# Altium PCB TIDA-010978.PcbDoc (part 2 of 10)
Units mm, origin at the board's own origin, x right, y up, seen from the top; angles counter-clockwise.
Board outline 243.95 x 94.85 mm, 4 copper layers (Top Layer, Mid Layer 1, Mid Layer 2, Bottom Layer), stack 1.623 mm thick; 865 components, 374 nets, 2308 pads, 2132 vias.
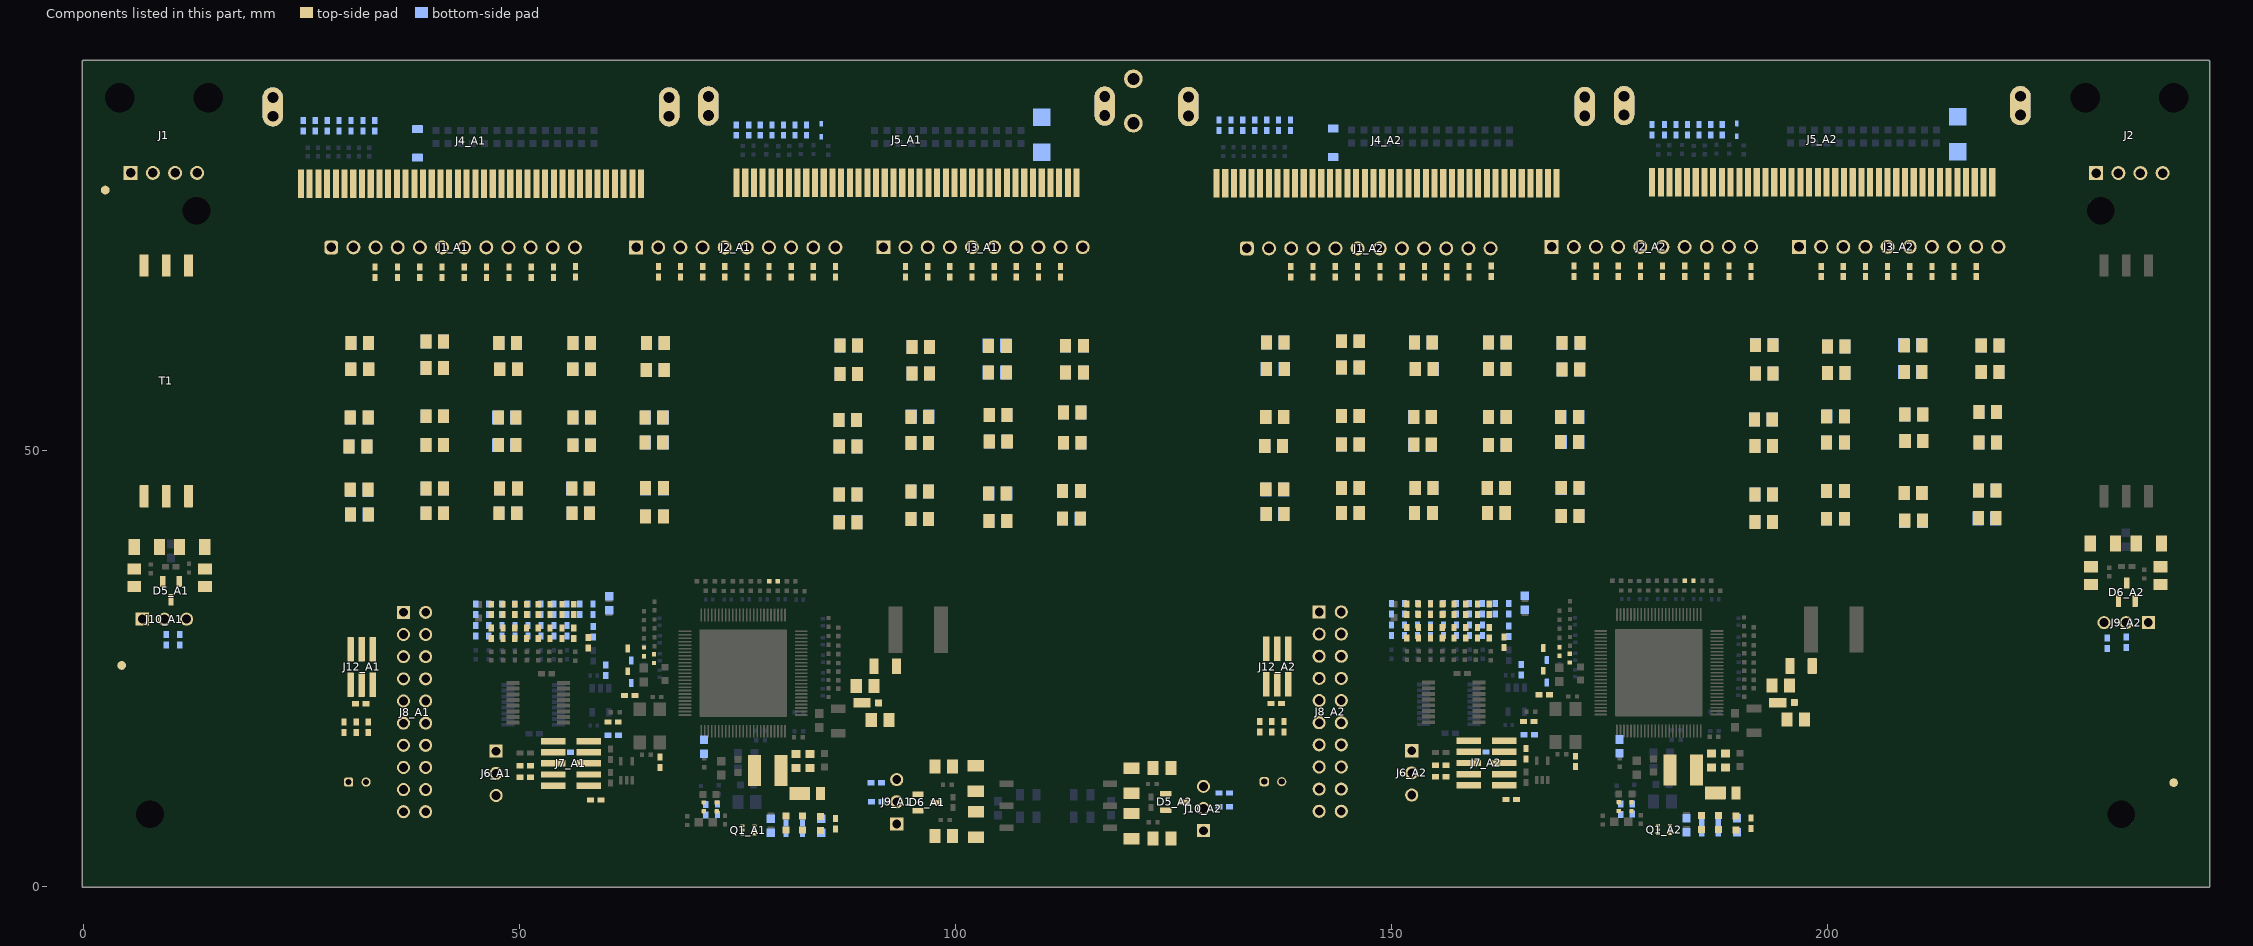
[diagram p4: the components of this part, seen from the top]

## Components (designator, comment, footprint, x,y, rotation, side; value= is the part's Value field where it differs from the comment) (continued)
C161_A2 "GCM155R71H104KE02D" 0402 165.428,15.207 r90 top value=0.1uF (schematic designator C161)
C162_A1 "885012205062" WCAP-CSGP_0402_L1W0.5H0.5 64.275,26.89 r90 top (schematic designator C162)
C162_A2 "885012205062" WCAP-CSGP_0402_L1W0.5H0.5 169.275,26.94 r90 top (schematic designator C162)
C163_A1 "885012205062" WCAP-CSGP_0402_L1W0.5H0.5 79.134,34.985 r0 top (schematic designator C163)
C163_A2 "885012205062" WCAP-CSGP_0402_L1W0.5H0.5 184.134,35.035 r0 top (schematic designator C163)
C164_A1 "885012205062" WCAP-CSGP_0402_L1W0.5H0.5 65.437,26.122 r90 top (schematic designator C164)
C164_A2 "885012205062" WCAP-CSGP_0402_L1W0.5H0.5 170.437,26.172 r90 top (schematic designator C164)
D1_A1 "SMAJ120A" SMA 109.917,86.187 r90 bottom value=120V (schematic designator D1)
D1_A2 "SMAJ120A" SMA 214.917,86.237 r90 bottom value=120V (schematic designator D1)
D2_A1 "MSP3V3-M3/89A" FP-MSP3V3-M3/89A_DO-219AD-MFG 89.932,21.045 r0 top (schematic designator D2)
D2_A2 "MSP3V3-M3/89A" FP-MSP3V3-M3/89A_DO-219AD-MFG 194.944,21.08 r0 top (schematic designator D2)
D3_A1 "DFLS1200Q-7" FP-DFLS1200Q-7_PowerDI123-MFG 82.994,10.671 r180 top (schematic designator D3)
D3_A2 "DFLS1200Q-7" FP-DFLS1200Q-7_PowerDI123-MFG 187.994,10.721 r180 top (schematic designator D3)
D4_A1 "TSD03DYFR" DYF0002A-MFG 62.822,24.614 r270 bottom (schematic designator D4)
D4_A2 "TSD03DYFR" DYF0002A-MFG 167.822,24.664 r270 bottom (schematic designator D4)
D5_A1 "ESD652DBZRQ1" DBZ0003A-MFG 10.044,33.917 r270 top (schematic designator D5)
D5_A2 "ESD652DBZRQ1" DBZ0003A-MFG 125.167,9.682 r0 top (schematic designator D5)
D6_A1 "ESD652DBZRQ1" DBZ0003A-MFG 96.754,9.621 r0 top (schematic designator D6)
D6_A2 "ESD652DBZRQ1" DBZ0003A-MFG 234.331,33.738 r90 top (schematic designator D6)
D7_A1 "SMD16PL-TP" FP-SMD16PL-TP_SOD123FL-MFG 38.313,85.209 r90 bottom (schematic designator D7)
D7_A2 "SMD16PL-TP" FP-SMD16PL-TP_SOD123FL-MFG 143.313,85.259 r90 bottom (schematic designator D7)
D8_A1 "TSD03DYFR" DYF0002A-MFG 62.422,25.974 r270 top (schematic designator D8)
D8_A2 "TSD03DYFR" DYF0002A-MFG 167.422,26.024 r270 top (schematic designator D8)
DVDD_LED1_A1 "150060GS75000" WL-SMCW_GREEN 82.479,7.262 r90 top value=Green (schematic designator DVDD_LED1)
DVDD_LED1_A2 "150060GS75000" WL-SMCW_GREEN 187.479,7.313 r90 top value=Green (schematic designator DVDD_LED1)
FID1 "Fiducial" Fiducial10-20 2.5,79.85 r0 top
FID2 "Fiducial" Fiducial10-20 4.373,25.336 r0 top
FID3 "Fiducial" Fiducial10-20 239.7,11.9 r0 top
H1 "MTG_NoPads" NPTH125mil 7.621,8.259 r0 top
H2 "MTG_NoPads" NPTH125mil 231.333,77.485 r0 top
H3 "MTG_NoPads" NPTH125mil 12.972,77.485 r0 top
H4 "MTG_NoPads" NPTH125mil 233.7,8.259 r0 top
J1 "70551-0038" Molex_70551-0038 9.23,81.81 r90 top
J1_A1 "61301211121" 61301211121 42.389,73.282 r0 top (schematic designator J1)
J1_A2 "61301211121" 61301211121 147.389,73.167 r0 top (schematic designator J1)
J2 "70551-0038" Molex_70551-0038 234.625,81.8 r90 top
J2_A1 "61301011121" Wurth_61301011121 74.803,73.282 r0 top (schematic designator J2)
J2_A2 "61301011121" Wurth_61301011121 179.803,73.332 r0 top (schematic designator J2)
J3_A1 "61301011121" Wurth_61301011121 103.165,73.295 r0 top (schematic designator J3)
J3_A2 "61301011121" Wurth_61301011121 208.165,73.345 r0 top (schematic designator J3)
J4_A1 "141114-214010" FP-141114-214010_HDR40-MFG 44.442,88.287 r180 top (schematic designator J4)
J4_A2 "141114-214010" FP-141114-214010_HDR40-MFG 149.442,88.337 r180 top (schematic designator J4)
J5_A1 "141115-214010" FP-141114-214010_HDR40-MFG 94.392,88.387 r180 top (schematic designator J5)
J5_A2 "141115-214010" FP-141114-214010_HDR40-MFG 199.392,88.437 r180 top (schematic designator J5)
J6_A1 "PEC03SAAN" CONN_PEC03SAAN 47.323,12.961 r270 top (schematic designator J6)
J6_A2 "PEC03SAAN" CONN_PEC03SAAN 152.323,13.011 r270 top (schematic designator J6)
J7_A1 "FTSH-105-01-L-DV-K" Samtec_FTSH-105-01-x-DV-K 55.895,14.101 r180 top (schematic designator J7)
J7_A2 "FTSH-105-01-L-DV-K" Samtec_FTSH-105-01-x-DV-K 160.895,14.151 r180 top (schematic designator J7)
J8_A1 "PRPC010DAAN-RC" Sullins_xxxC010DAAN 37.973,19.991 r0 top (schematic designator J8)
J8_A2 "PRPC010DAAN-RC" Sullins_xxxC010DAAN 142.973,20.041 r0 top (schematic designator J8)
J9_A1 "PEC03SAAN" CONN_PEC03SAAN 93.264,9.702 r90 top (schematic designator J9)
J9_A2 "PEC03SAAN" CONN_PEC03SAAN 234.25,30.248 r180 top (schematic designator J9)
J10_A1 "PEC03SAAN" CONN_PEC03SAAN 9.287,30.642 r0 top (schematic designator J10)
J10_A2 "PEC03SAAN" CONN_PEC03SAAN 128.442,8.926 r90 top (schematic designator J10)
J11_A1 "B2B-PH-K-S(LF)(SN)" JST_B2B-PH-K-S 31.413,11.405 r0 top (schematic designator J11)
J11_A2 "B2B-PH-K-S(LF)(SN)" JST_B2B-PH-K-S 136.413,11.455 r0 top (schematic designator J11)
J12_A1 "FTSH-103-01-L-DV-K" FP-FTSH-103-01-F-DV-TR_HDR6-MFG 31.901,25.161 r180 top (schematic designator J12)
J12_A2 "FTSH-103-01-L-DV-K" FP-FTSH-103-01-F-DV-TR_HDR6-MFG 136.901,25.211 r180 top (schematic designator J12)
j13 "63824-1" FP-63824-1_CONN_7MM92_3MM11-MFG 120.4,90.062 r270 top (schematic designator J13)
L2_A1 "74404042101" WE-LQS_4018 78.468,13.29 r180 top (schematic designator L2)
L2_A2 "74404042101" WE-LQS_4018 183.468,13.34 r180 top (schematic designator L2)
LBL1 "THT-14-423-10" Label_650x200 219.021,6.766 r0 top
LDOIN_LED1_A1 "150060GS75000" WL-SMCW_GREEN 80.571,7.262 r90 top value=Green (schematic designator LDOIN_LED1)
LDOIN_LED1_A2 "150060GS75000" WL-SMCW_GREEN 185.571,7.313 r90 top value=Green (schematic designator LDOIN_LED1)
Logo1 "Texas Instruments" TI_Stacked_Overlay_Small 218.143,28.378 r0 top
Logo2 "CE Mark" CE_Mark_5mm 217.099,15.808 r0 top
Logo3 "FCC disclaimer" FCC_disclaimer 216.878,2.683 r0 top
Logo4 "WEEE logo" WEEE_Minimum 224.561,16.126 r0 top
LOGO5 "DANGER HIGH VOLTAGE" IEC_HighVoltage_Small 209.565,16.126 r0 top
NFAULT_LED1_A1 "150060RS75000" WL-SMCW_RED 84.517,7.212 r90 top value=Red (schematic designator NFAULT_LED1)
NFAULT_LED1_A2 "150060RS75000" WL-SMCW_RED 189.517,7.263 r90 top value=Red (schematic designator NFAULT_LED1)
Q1_A1 "SSM6L56FE,LM" FP-SSM6L56FE,LM_SOT563-MFG 76.262,6.465 r270 top (schematic designator Q1)
Q1_A2 "SSM6L56FE,LM" FP-SSM6L56FE,LM_SOT563-MFG 181.262,6.515 r270 top (schematic designator Q1)
R1_A1 "CRCW080528R0FKEA" 0805_HV 89.642,22.984 r0 top value=28.0 (schematic designator R1)
R1_A2 "CRCW080528R0FKEA" 0805_HV 194.642,23.034 r0 top value=28.0 (schematic designator R1)
R2_A1 "HPCR0805J68R0KT" 0805_HV 48.674,42.787 r0 top value=68 (schematic designator R2)
R2_A2 "HPCR0805J68R0KT" 0805_HV 153.674,42.837 r0 top value=68 (schematic designator R2)
R3_A1 "HPCR0805J68R0KT" 0805_HV 65.486,45.662 r0 top value=68 (schematic designator R3)
R3_A2 "HPCR0805J68R0KT" 0805_HV 170.486,45.712 r0 top value=68 (schematic designator R3)
R4_A1 "HPCR0805J68R0KT" 0805_HV 95.914,42.111 r0 bottom value=68 (schematic designator R4)
R4_A2 "HPCR0805J68R0KT" 0805_HV 200.914,42.161 r0 bottom value=68 (schematic designator R4)
R5_A1 "HPCR0805J68R0KT" 0805_HV 113.313,45.358 r0 top value=68 (schematic designator R5)
R5_A2 "HPCR0805J68R0KT" 0805_HV 218.313,45.408 r0 top value=68 (schematic designator R5)
R6_A1 "CRCW120662R0JNEAHP" FP-CRCW120662R0JNEAHP_1206-MFG 91.952,25.245 r0 top value=62 (schematic designator R6)
R6_A2 "CRCW120662R0JNEAHP" FP-CRCW120662R0JNEAHP_1206-MFG 196.979,25.277 r0 top value=62 (schematic designator R6)
R7_A1 "CRCW080551R0JNEA" 0805_HV 91.358,19.092 r180 top value=51 (schematic designator R7)
R7_A2 "CRCW080551R0JNEA" 0805_HV 196.358,19.142 r180 top value=51 (schematic designator R7)
R8_A1 "HPCR0805J68R0KT" 0805_HV 48.744,45.646 r0 top value=68 (schematic designator R8)
R8_A2 "HPCR0805J68R0KT" 0805_HV 153.744,45.696 r0 top value=68 (schematic designator R8)
R9_A1 "HPCR0805J68R0KT" 0805_HV 65.486,42.446 r0 bottom value=68 (schematic designator R9)
R9_A2 "HPCR0805J68R0KT" 0805_HV 170.486,42.496 r0 bottom value=68 (schematic designator R9)
R10_A1 "HPCR0805J68R0KT" 0805_HV 95.914,45.279 r0 top value=68 (schematic designator R10)
R10_A2 "HPCR0805J68R0KT" 0805_HV 200.914,45.329 r0 top value=68 (schematic designator R10)
R11_A1 "HPCR0805J68R0KT" 0805_HV 113.313,42.205 r0 top value=68 (schematic designator R11)
R11_A2 "HPCR0805J68R0KT" 0805_HV 218.313,42.255 r0 top value=68 (schematic designator R11)
R12_A1 "HPCR0805J68R0KT" 0805_HV 48.674,42.787 r0 bottom value=68 (schematic designator R12)
R12_A2 "HPCR0805J68R0KT" 0805_HV 153.674,42.837 r0 bottom value=68 (schematic designator R12)
R13_A1 "HPCR0805J68R0KT" 0805_HV 65.486,45.646 r0 bottom value=68 (schematic designator R13)
R13_A2 "HPCR0805J68R0KT" 0805_HV 170.486,45.696 r0 bottom value=68 (schematic designator R13)
R14_A1 "HPCR0805J68R0KT" 0805_HV 95.914,45.279 r0 bottom value=68 (schematic designator R14)
R14_A2 "HPCR0805J68R0KT" 0805_HV 200.914,45.329 r0 bottom value=68 (schematic designator R14)
R15_A1 "HPCR0805J68R0KT" 0805_HV 113.273,42.157 r0 bottom value=68 (schematic designator R15)
R15_A2 "HPCR0805J68R0KT" 0805_HV 218.273,42.207 r0 bottom value=68 (schematic designator R15)
R16_A1 "HPCR0805J68R0KT" 0805_HV 48.744,45.646 r0 bottom value=68 (schematic designator R16)
R16_A2 "HPCR0805J68R0KT" 0805_HV 153.744,45.696 r0 bottom value=68 (schematic designator R16)
R17_A1 "HPCR0805J68R0KT" 0805_HV 65.486,42.437 r0 top value=68 (schematic designator R17)
R17_A2 "HPCR0805J68R0KT" 0805_HV 170.486,42.487 r0 top value=68 (schematic designator R17)
R18_A1 "HPCR0805J68R0KT" 0805_HV 95.914,42.111 r0 top value=68 (schematic designator R18)
R18_A2 "HPCR0805J68R0KT" 0805_HV 200.914,42.161 r0 top value=68 (schematic designator R18)
R19_A1 "HPCR0805J68R0KT" 0805_HV 113.313,45.325 r0 bottom value=68 (schematic designator R19)
R19_A2 "HPCR0805J68R0KT" 0805_HV 218.313,45.375 r0 bottom value=68 (schematic designator R19)
R20_A1 "DNP" 0603 82.507,13.585 r180 top value=10 (schematic designator R20)
R20_A2 "DNP" 0603 187.507,13.635 r180 top value=10 (schematic designator R20)
R21_A1 "HPCR0805J68R0KT" 0805_HV 40.291,59.461 r0 top value=68 (schematic designator R21)
R21_A2 "HPCR0805J68R0KT" 0805_HV 145.291,59.511 r0 top value=68 (schematic designator R21)
R22_A1 "HPCR0805J68R0KT" 0805_HV 57.146,62.305 r0 top value=68 (schematic designator R22)
R22_A2 "HPCR0805J68R0KT" 0805_HV 162.146,62.355 r0 top value=68 (schematic designator R22)
R23_A1 "HPCR0805J68R0KT" 0805_HV 87.758,58.747 r0 top value=68 (schematic designator R23)
R23_A2 "HPCR0805J68R0KT" 0805_HV 192.758,58.797 r0 top value=68 (schematic designator R23)
R24_A1 "HPCR0805J68R0KT" 0805_HV 104.828,58.946 r0 top value=68 (schematic designator R24)
R24_A2 "HPCR0805J68R0KT" 0805_HV 209.828,58.996 r0 top value=68 (schematic designator R24)
R25_A1 "HPCR0805J68R0KT" 0805_HV 40.291,62.462 r0 bottom value=68 (schematic designator R25)
R25_A2 "HPCR0805J68R0KT" 0805_HV 145.291,62.512 r0 bottom value=68 (schematic designator R25)
R26_A1 "HPCR0805J68R0KT" 0805_HV 57.129,59.305 r0 top value=68 (schematic designator R26)
R26_A2 "HPCR0805J68R0KT" 0805_HV 162.129,59.355 r0 top value=68 (schematic designator R26)
R27_A1 "HPCR0805J68R0KT" 0805_HV 87.758,62.003 r0 top value=68 (schematic designator R27)
R27_A2 "HPCR0805J68R0KT" 0805_HV 192.758,62.053 r0 top value=68 (schematic designator R27)
R28_A1 "HPCR0805J68R0KT" 0805_HV 104.748,58.946 r0 bottom value=68 (schematic designator R28)
R28_A2 "HPCR0805J68R0KT" 0805_HV 209.748,58.996 r0 bottom value=68 (schematic designator R28)
R29_A1 "HPCR0805J68R0KT" 0805_HV 40.291,59.461 r0 bottom value=68 (schematic designator R29)
R29_A2 "HPCR0805J68R0KT" 0805_HV 145.291,59.511 r0 bottom value=68 (schematic designator R29)
R30_A1 "HPCR0805J68R0KT" 0805_HV 57.129,59.305 r0 bottom value=68 (schematic designator R30)
R30_A2 "HPCR0805J68R0KT" 0805_HV 162.129,59.355 r0 bottom value=68 (schematic designator R30)
R31_A1 "HPCR0805J68R0KT" 0805_HV 87.758,58.747 r0 bottom value=68 (schematic designator R31)
R31_A2 "HPCR0805J68R0KT" 0805_HV 192.758,58.797 r0 bottom value=68 (schematic designator R31)
R32_A1 "HPCR0805J68R0KT" 0805_HV 104.748,62.012 r0 bottom value=68 (schematic designator R32)
R32_A2 "HPCR0805J68R0KT" 0805_HV 209.748,62.062 r0 bottom value=68 (schematic designator R32)
R33_A1 "HPCR0805J68R0KT" 0805_HV 40.291,62.462 r0 top value=68 (schematic designator R33)
R33_A2 "HPCR0805J68R0KT" 0805_HV 145.291,62.512 r0 top value=68 (schematic designator R33)
R34_A1 "HPCR0805J68R0KT" 0805_HV 57.146,62.305 r0 bottom value=68 (schematic designator R34)
R34_A2 "HPCR0805J68R0KT" 0805_HV 162.146,62.355 r0 bottom value=68 (schematic designator R34)
R35_A1 "HPCR0805J68R0KT" 0805_HV 87.758,62.012 r0 bottom value=68 (schematic designator R35)
R35_A2 "HPCR0805J68R0KT" 0805_HV 192.758,62.062 r0 bottom value=68 (schematic designator R35)
R36_A1 "HPCR0805J68R0KT" 0805_HV 104.828,61.969 r0 top value=68 (schematic designator R36)
R36_A2 "HPCR0805J68R0KT" 0805_HV 209.828,62.019 r0 top value=68 (schematic designator R36)
R37_A1 "RC0603FR-07120RL" 0603 71.159,16.004 r270 bottom value=120 (schematic designator R37)
R37_A2 "RC0603FR-07120RL" 0603 176.159,16.054 r270 bottom value=120 (schematic designator R37)
R38_A1 "HPCR0805J68R0KT" 0805_HV 40.291,50.603 r0 top value=68 (schematic designator R38)
R38_A2 "HPCR0805J68R0KT" 0805_HV 145.291,50.653 r0 top value=68 (schematic designator R38)
R39_A1 "HPCR0805J68R0KT" 0805_HV 57.146,53.755 r0 top value=68 (schematic designator R39)
R39_A2 "HPCR0805J68R0KT" 0805_HV 162.146,53.805 r0 top value=68 (schematic designator R39)
R40_A1 "HPCR0805J68R0KT" 0805_HV 87.688,50.464 r0 top value=68 (schematic designator R40)
R40_A2 "HPCR0805J68R0KT" 0805_HV 192.688,50.514 r0 top value=68 (schematic designator R40)
R41_A1 "HPCR0805J68R0KT" 0805_HV 104.915,54.059 r0 top value=68 (schematic designator R41)
R41_A2 "HPCR0805J68R0KT" 0805_HV 209.915,54.109 r0 top value=68 (schematic designator R41)
R42_A1 "HPCR0805J68R0KT" 0805_HV 40.291,53.912 r0 top value=68 (schematic designator R42)
R42_A2 "HPCR0805J68R0KT" 0805_HV 145.291,53.962 r0 top value=68 (schematic designator R42)
R43_A1 "HPCR0805J68R0KT" 0805_HV 57.146,50.587 r0 top value=68 (schematic designator R43)
R43_A2 "HPCR0805J68R0KT" 0805_HV 162.146,50.637 r0 top value=68 (schematic designator R43)
R44_A1 "HPCR0805J68R0KT" 0805_HV 87.649,53.464 r0 top value=68 (schematic designator R44)
R44_A2 "HPCR0805J68R0KT" 0805_HV 192.649,53.514 r0 top value=68 (schematic designator R44)
R45_A1 "HPCR0805J68R0KT" 0805_HV 104.857,51.025 r0 bottom value=68 (schematic designator R45)
R45_A2 "HPCR0805J68R0KT" 0805_HV 209.857,51.075 r0 bottom value=68 (schematic designator R45)
R46_A1 "HPCR0805J68R0KT" 0805_HV 40.291,53.912 r0 bottom value=68 (schematic designator R46)
R46_A2 "HPCR0805J68R0KT" 0805_HV 145.291,53.962 r0 bottom value=68 (schematic designator R46)
R47_A1 "HPCR0805J68R0KT" 0805_HV 57.146,53.755 r0 bottom value=68 (schematic designator R47)
R47_A2 "HPCR0805J68R0KT" 0805_HV 162.146,53.805 r0 bottom value=68 (schematic designator R47)
R48_A1 "HPCR0805J68R0KT" 0805_HV 87.688,50.464 r0 bottom value=68 (schematic designator R48)
R48_A2 "HPCR0805J68R0KT" 0805_HV 192.688,50.514 r0 bottom value=68 (schematic designator R48)
R49_A1 "HPCR0805J68R0KT" 0805_HV 104.877,54.059 r0 bottom value=68 (schematic designator R49)
R49_A2 "HPCR0805J68R0KT" 0805_HV 209.877,54.109 r0 bottom value=68 (schematic designator R49)
R50_A1 "ERJ-3GEY0R00V" 0603 82.507,15.19 r0 top value=0 (schematic designator R50)
R50_A2 "ERJ-3GEY0R00V" 0603 187.507,15.24 r0 top value=0 (schematic designator R50)
R51_A1 "HPCR0805J68R0KT" 0805_HV 40.291,50.603 r0 bottom value=68 (schematic designator R51)
R51_A2 "HPCR0805J68R0KT" 0805_HV 145.291,50.653 r0 bottom value=68 (schematic designator R51)
R52_A1 "HPCR0805J68R0KT" 0805_HV 57.146,50.587 r0 bottom value=68 (schematic designator R52)
R52_A2 "HPCR0805J68R0KT" 0805_HV 162.146,50.637 r0 bottom value=68 (schematic designator R52)
R53_A1 "HPCR0805J68R0KT" 0805_HV 87.649,53.464 r0 bottom value=68 (schematic designator R53)
R53_A2 "HPCR0805J68R0KT" 0805_HV 192.649,53.514 r0 bottom value=68 (schematic designator R53)
R54_A1 "HPCR0805J68R0KT" 0805_HV 104.941,51.025 r0 top value=68 (schematic designator R54)
R54_A2 "HPCR0805J68R0KT" 0805_HV 209.941,51.075 r0 top value=68 (schematic designator R54)
R55_A1 "ERJ-2RKF10R0X" FP-ERJ-2RKF10R0X_0402-MFG 71.154,9.122 r270 top (schematic designator R55)
R55_A2 "ERJ-2RKF10R0X" FP-ERJ-2RKF10R0X_0402-MFG 176.056,9.14 r270 top (schematic designator R55)
R56_A1 "CRCW040210K2FKED" 0402 60.767,17.341 r180 bottom value=10.2k (schematic designator R56)
R56_A2 "CRCW040210K2FKED" 0402 165.817,17.391 r180 bottom value=10.2k (schematic designator R56)
R57_A1 "ERJ-2RKF10R0X" FP-ERJ-2RKF10R0X_0402-MFG 72.629,9.121 r270 top (schematic designator R57)
R57_A2 "ERJ-2RKF10R0X" FP-ERJ-2RKF10R0X_0402-MFG 177.531,9.137 r270 top (schematic designator R57)
R58_A1 "HPCR0805J68R0KT" 0805_HV 40.291,42.787 r0 top value=68 (schematic designator R58)
R58_A2 "HPCR0805J68R0KT" 0805_HV 145.291,42.837 r0 top value=68 (schematic designator R58)
R59_A1 "HPCR0805J68R0KT" 0805_HV 57.03,45.637 r0 top value=68 (schematic designator R59)
R59_A2 "HPCR0805J68R0KT" 0805_HV 162.03,45.687 r0 top value=68 (schematic designator R59)
R60_A1 "HPCR0805J68R0KT" 0805_HV 87.688,44.914 r0 bottom value=68 (schematic designator R60)
R60_A2 "HPCR0805J68R0KT" 0805_HV 192.688,44.964 r0 bottom value=68 (schematic designator R60)
R61_A1 "HPCR0805J68R0KT" 0805_HV 104.866,45.078 r0 bottom value=68 (schematic designator R61)
R61_A2 "HPCR0805J68R0KT" 0805_HV 209.866,45.128 r0 bottom value=68 (schematic designator R61)
R62_A1 "HPCR0805J68R0KT" 0805_HV 40.291,42.787 r0 bottom value=68 (schematic designator R62)
R62_A2 "HPCR0805J68R0KT" 0805_HV 145.291,42.837 r0 bottom value=68 (schematic designator R62)
R63_A1 "HPCR0805J68R0KT" 0805_HV 57.03,42.787 r0 bottom value=68 (schematic designator R63)
R63_A2 "HPCR0805J68R0KT" 0805_HV 162.03,42.837 r0 bottom value=68 (schematic designator R63)
R64_A1 "HPCR0805J68R0KT" 0805_HV 87.688,41.746 r0 top value=68 (schematic designator R64)
R64_A2 "HPCR0805J68R0KT" 0805_HV 192.688,41.796 r0 top value=68 (schematic designator R64)
R65_A1 "HPCR0805J68R0KT" 0805_HV 104.782,45.078 r0 top value=68 (schematic designator R65)
R65_A2 "HPCR0805J68R0KT" 0805_HV 209.782,45.128 r0 top value=68 (schematic designator R65)
R66_A1 "HPCR0805J68R0KT" 0805_HV 40.291,45.646 r0 top value=68 (schematic designator R66)
R66_A2 "HPCR0805J68R0KT" 0805_HV 145.291,45.696 r0 top value=68 (schematic designator R66)
R67_A1 "HPCR0805J68R0KT" 0805_HV 57.03,42.787 r0 top value=68 (schematic designator R67)
R67_A2 "HPCR0805J68R0KT" 0805_HV 162.03,42.837 r0 top value=68 (schematic designator R67)
R68_A1 "HPCR0805J68R0KT" 0805_HV 87.688,44.914 r0 top value=68 (schematic designator R68)
R68_A2 "HPCR0805J68R0KT" 0805_HV 192.688,44.964 r0 top value=68 (schematic designator R68)
R69_A1 "HPCR0805J68R0KT" 0805_HV 104.857,41.876 r0 bottom value=68 (schematic designator R69)
R69_A2 "HPCR0805J68R0KT" 0805_HV 209.857,41.926 r0 bottom value=68 (schematic designator R69)
R70_A1 "ERJ-2GE0R00X" 0402 59.887,24.806 r90 bottom value=0 (schematic designator R70)
R70_A2 "ERJ-2GE0R00X" 0402 164.887,24.856 r90 bottom value=0 (schematic designator R70)
R71_A1 "ERJ-2GE0R00X" 0402 66.111,14.231 r270 top value=0 (schematic designator R71)
R71_A2 "ERJ-2GE0R00X" 0402 171.104,14.321 r270 top value=0 (schematic designator R71)
R72_A1 "HPCR0805J68R0KT" 0805_HV 40.291,45.637 r0 bottom value=68 (schematic designator R72)
R72_A2 "HPCR0805J68R0KT" 0805_HV 145.291,45.687 r0 bottom value=68 (schematic designator R72)
R73_A1 "HPCR0805J68R0KT" 0805_HV 56.964,45.646 r0 bottom value=68 (schematic designator R73)
R73_A2 "HPCR0805J68R0KT" 0805_HV 161.964,45.696 r0 bottom value=68 (schematic designator R73)
R74_A1 "HPCR0805J68R0KT" 0805_HV 87.688,41.762 r0 bottom value=68 (schematic designator R74)
R74_A2 "HPCR0805J68R0KT" 0805_HV 192.688,41.812 r0 bottom value=68 (schematic designator R74)
R75_A1 "HPCR0805J68R0KT" 0805_HV 104.877,41.925 r0 top value=68 (schematic designator R75)
R75_A2 "HPCR0805J68R0KT" 0805_HV 209.877,41.975 r0 top value=68 (schematic designator R75)
R76_A1 "CRCW040210K2FKED" 0402 60.728,18.845 r0 top value=10.2k (schematic designator R76)
R76_A2 "CRCW040210K2FKED" 0402 165.728,18.895 r0 top value=10.2k (schematic designator R76)
R77_A1 "ERJ-2GE0R00X" 0402 62.667,21.882 r180 top value=0 (schematic designator R77)
R77_A2 "ERJ-2GE0R00X" 0402 167.515,21.964 r180 top value=0 (schematic designator R77)
R78_A1 "ERJ-2GE0R00X" 0402 71.375,8.812 r270 bottom value=0 (schematic designator R78)
R78_A2 "ERJ-2GE0R00X" 0402 176.287,8.861 r270 bottom value=0 (schematic designator R78)
R79_A1 "ERJ-2GE0R00X" 0402 86.233,7.167 r90 top value=0 (schematic designator R79)
R79_A2 "ERJ-2GE0R00X" 0402 191.233,7.217 r90 top value=0 (schematic designator R79)
R80_A1 "HPCR0805J68R0KT" 0805_HV 31.65,59.305 r0 bottom value=68 (schematic designator R80)
R80_A2 "HPCR0805J68R0KT" 0805_HV 136.65,59.355 r0 bottom value=68 (schematic designator R80)
R81_A1 "HPCR0805J68R0KT" 0805_HV 48.744,59.305 r0 top value=68 (schematic designator R81)
R81_A2 "HPCR0805J68R0KT" 0805_HV 153.744,59.355 r0 top value=68 (schematic designator R81)
R82_A1 "HPCR0805J68R0KT" 0805_HV 65.559,59.227 r0 top value=68 (schematic designator R82)
R82_A2 "HPCR0805J68R0KT" 0805_HV 170.559,59.277 r0 top value=68 (schematic designator R82)
R83_A1 "HPCR0805J68R0KT" 0805_HV 96.01,61.844 r0 top value=68 (schematic designator R83)
R83_A2 "HPCR0805J68R0KT" 0805_HV 201.01,61.894 r0 top value=68 (schematic designator R83)
R84_A1 "HPCR0805J68R0KT" 0805_HV 113.651,58.928 r0 top value=68 (schematic designator R84)
R84_A2 "HPCR0805J68R0KT" 0805_HV 218.651,58.978 r0 top value=68 (schematic designator R84)
R85_A1 "HPCR0805J68R0KT" 0805_HV 31.679,62.305 r0 bottom value=68 (schematic designator R85)
R85_A2 "HPCR0805J68R0KT" 0805_HV 136.679,62.355 r0 bottom value=68 (schematic designator R85)
R86_A1 "HPCR0805J68R0KT" 0805_HV 48.662,62.305 r0 top value=68 (schematic designator R86)
R86_A2 "HPCR0805J68R0KT" 0805_HV 153.662,62.355 r0 top value=68 (schematic designator R86)
R87_A1 "HPCR0805J68R0KT" 0805_HV 65.59,62.292 r0 top value=68 (schematic designator R87)
R87_A2 "HPCR0805J68R0KT" 0805_HV 170.59,62.342 r0 top value=68 (schematic designator R87)
R88_A1 "HPCR0805J68R0KT" 0805_HV 96.015,58.821 r0 top value=68 (schematic designator R88)
R88_A2 "HPCR0805J68R0KT" 0805_HV 201.015,58.871 r0 top value=68 (schematic designator R88)
R89_A1 "HPCR0805J68R0KT" 0805_HV 113.651,61.996 r0 top value=68 (schematic designator R89)
R89_A2 "HPCR0805J68R0KT" 0805_HV 218.651,62.046 r0 top value=68 (schematic designator R89)
R90_A1 "HPCR0805J68R0KT" 0805_HV 31.679,62.305 r0 top value=68 (schematic designator R90)
R90_A2 "HPCR0805J68R0KT" 0805_HV 136.679,62.355 r0 top value=68 (schematic designator R90)
R91_A1 "HPCR0805J68R0KT" 0805_HV 48.78,59.305 r0 bottom value=68 (schematic designator R91)
R91_A2 "HPCR0805J68R0KT" 0805_HV 153.78,59.355 r0 bottom value=68 (schematic designator R91)
R92_A1 "HPCR0805J68R0KT" 0805_HV 65.59,59.227 r0 bottom value=68 (schematic designator R92)
R92_A2 "HPCR0805J68R0KT" 0805_HV 170.59,59.277 r0 bottom value=68 (schematic designator R92)
R93_A1 "HPCR0805J68R0KT" 0805_HV 96.015,58.821 r0 bottom value=68 (schematic designator R93)
R93_A2 "HPCR0805J68R0KT" 0805_HV 201.015,58.871 r0 bottom value=68 (schematic designator R93)
R94_A1 "HPCR0805J68R0KT" 0805_HV 113.651,61.996 r0 bottom value=68 (schematic designator R94)
R94_A2 "HPCR0805J68R0KT" 0805_HV 218.651,62.046 r0 bottom value=68 (schematic designator R94)
R95_A1 "HPCR0805J68R0KT" 0805_HV 31.704,59.305 r0 top value=68 (schematic designator R95)
R95_A2 "HPCR0805J68R0KT" 0805_HV 136.704,59.355 r0 top value=68 (schematic designator R95)
R96_A1 "HPCR0805J68R0KT" 0805_HV 48.638,62.305 r0 bottom value=68 (schematic designator R96)
R96_A2 "HPCR0805J68R0KT" 0805_HV 153.638,62.355 r0 bottom value=68 (schematic designator R96)
R97_A1 "HPCR0805J68R0KT" 0805_HV 65.59,62.283 r0 bottom value=68 (schematic designator R97)
R97_A2 "HPCR0805J68R0KT" 0805_HV 170.59,62.333 r0 bottom value=68 (schematic designator R97)
R98_A1 "HPCR0805J68R0KT" 0805_HV 96.015,61.844 r0 bottom value=68 (schematic designator R98)
R98_A2 "HPCR0805J68R0KT" 0805_HV 201.015,61.894 r0 bottom value=68 (schematic designator R98)
R99_A1 "HPCR0805J68R0KT" 0805_HV 113.651,58.928 r0 bottom value=68 (schematic designator R99)
R99_A2 "HPCR0805J68R0KT" 0805_HV 218.651,58.978 r0 bottom value=68 (schematic designator R99)
R100_A1 "HPCR0805J68R0KT" 0805_HV 31.602,53.755 r0 top value=68 (schematic designator R100)
R100_A2 "HPCR0805J68R0KT" 0805_HV 136.602,53.805 r0 top value=68 (schematic designator R100)
R101_A1 "HPCR0805J68R0KT" 0805_HV 48.524,50.587 r0 bottom value=68 (schematic designator R101)
R101_A2 "HPCR0805J68R0KT" 0805_HV 153.524,50.637 r0 bottom value=68 (schematic designator R101)
R102_A1 "HPCR0805J68R0KT" 0805_HV 65.472,53.79 r0 bottom value=68 (schematic designator R102)
R102_A2 "HPCR0805J68R0KT" 0805_HV 170.472,53.84 r0 bottom value=68 (schematic designator R102)
R103_A1 "HPCR0805J68R0KT" 0805_HV 95.914,53.829 r0 top value=68 (schematic designator R103)
R103_A2 "HPCR0805J68R0KT" 0805_HV 200.914,53.879 r0 top value=68 (schematic designator R103)
R104_A1 "HPCR0805J68R0KT" 0805_HV 113.388,54.34 r0 top value=68 (schematic designator R104)
R104_A2 "HPCR0805J68R0KT" 0805_HV 218.388,54.39 r0 top value=68 (schematic designator R104)
R105_A1 "ERJ-2GE0R00X" 0402 72.697,8.826 r90 bottom value=0 (schematic designator R105)
R105_A2 "ERJ-2GE0R00X" 0402 177.609,8.874 r90 bottom value=0 (schematic designator R105)
R107_A1 "HPCR0805J68R0KT" 0805_HV 31.48,50.446 r0 top value=68 (schematic designator R107)
R107_A2 "HPCR0805J68R0KT" 0805_HV 136.48,50.496 r0 top value=68 (schematic designator R107)
R108_A1 "HPCR0805J68R0KT" 0805_HV 48.59,53.755 r0 top value=68 (schematic designator R108)
R108_A2 "HPCR0805J68R0KT" 0805_HV 153.59,53.805 r0 top value=68 (schematic designator R108)
R109_A1 "HPCR0805J68R0KT" 0805_HV 65.416,53.79 r0 top value=68 (schematic designator R109)
R109_A2 "HPCR0805J68R0KT" 0805_HV 170.416,53.84 r0 top value=68 (schematic designator R109)
R110_A1 "HPCR0805J68R0KT" 0805_HV 95.946,53.862 r0 bottom value=68 (schematic designator R110)
R110_A2 "HPCR0805J68R0KT" 0805_HV 200.946,53.912 r0 bottom value=68 (schematic designator R110)
R111_A1 "HPCR0805J68R0KT" 0805_HV 113.388,50.874 r0 top value=68 (schematic designator R111)
R111_A2 "HPCR0805J68R0KT" 0805_HV 218.388,50.924 r0 top value=68 (schematic designator R111)
R112_A1 "HPCR0805J68R0KT" 0805_HV 31.65,53.755 r0 bottom value=68 (schematic designator R112)
R112_A2 "HPCR0805J68R0KT" 0805_HV 136.65,53.805 r0 bottom value=68 (schematic designator R112)
R113_A1 "HPCR0805J68R0KT" 0805_HV 48.59,50.603 r0 top value=68 (schematic designator R113)
R113_A2 "HPCR0805J68R0KT" 0805_HV 153.59,50.653 r0 top value=68 (schematic designator R113)
R114_A1 "HPCR0805J68R0KT" 0805_HV 65.416,50.915 r0 top value=68 (schematic designator R114)
R114_A2 "HPCR0805J68R0KT" 0805_HV 170.416,50.965 r0 top value=68 (schematic designator R114)
R115_A1 "HPCR0805J68R0KT" 0805_HV 95.914,50.828 r0 bottom value=68 (schematic designator R115)
R115_A2 "HPCR0805J68R0KT" 0805_HV 200.914,50.878 r0 bottom value=68 (schematic designator R115)
R116_A1 "HPCR0805J68R0KT" 0805_HV 113.388,50.874 r0 bottom value=68 (schematic designator R116)
R116_A2 "HPCR0805J68R0KT" 0805_HV 218.388,50.924 r0 bottom value=68 (schematic designator R116)
R117_A1 "HPCR0805J68R0KT" 0805_HV 31.48,50.446 r0 bottom value=68 (schematic designator R117)
R117_A2 "HPCR0805J68R0KT" 0805_HV 136.48,50.496 r0 bottom value=68 (schematic designator R117)
R118_A1 "HPCR0805J68R0KT" 0805_HV 48.524,53.755 r0 bottom value=68 (schematic designator R118)
R118_A2 "HPCR0805J68R0KT" 0805_HV 153.524,53.805 r0 bottom value=68 (schematic designator R118)
R119_A1 "HPCR0805J68R0KT" 0805_HV 65.486,50.915 r0 bottom value=68 (schematic designator R119)
R119_A2 "HPCR0805J68R0KT" 0805_HV 170.486,50.965 r0 bottom value=68 (schematic designator R119)
R120_A1 "HPCR0805J68R0KT" 0805_HV 95.914,50.828 r0 top value=68 (schematic designator R120)
R120_A2 "HPCR0805J68R0KT" 0805_HV 200.914,50.878 r0 top value=68 (schematic designator R120)
R121_A1 "HPCR0805J68R0KT" 0805_HV 113.388,54.34 r0 bottom value=68 (schematic designator R121)
R121_A2 "HPCR0805J68R0KT" 0805_HV 218.388,54.39 r0 bottom value=68 (schematic designator R121)
R122_A1 "HPCR0805J68R0KT" 0805_HV 31.602,45.489 r0 top value=68 (schematic designator R122)
R122_A2 "HPCR0805J68R0KT" 0805_HV 136.602,45.539 r0 top value=68 (schematic designator R122)
R123_A1 "HPCR0805J68R0KT" 0805_HV 31.629,42.63 r0 bottom value=68 (schematic designator R123)
R123_A2 "HPCR0805J68R0KT" 0805_HV 136.629,42.68 r0 bottom value=68 (schematic designator R123)
R124_A1 "HPCR0805J68R0KT" 0805_HV 31.629,45.48 r0 bottom value=68 (schematic designator R124)
R124_A2 "HPCR0805J68R0KT" 0805_HV 136.629,45.53 r0 bottom value=68 (schematic designator R124)
R125_A1 "HPCR0805J68R0KT" 0805_HV 31.654,42.63 r0 top value=68 (schematic designator R125)
R125_A2 "HPCR0805J68R0KT" 0805_HV 136.654,42.68 r0 top value=68 (schematic designator R125)
R126_A1 "RC0402FR-074K7L" 0402 82.468,6.66 r270 bottom value=4.70k (schematic designator R126)
R126_A2 "RC0402FR-074K7L" 0402 187.468,6.71 r270 bottom value=4.70k (schematic designator R126)
R127_A1 "ESR03EZPJ102" 0603 60.292,32.471 r270 bottom value=1.0k (schematic designator R127)
R127_A2 "ESR03EZPJ102" 0603 165.292,32.521 r270 bottom value=1.0k (schematic designator R127)
R128_A1 "ESR03EZPJ102" 0603 78.833,6.964 r90 bottom value=1.0k (schematic designator R128)
R128_A2 "ESR03EZPJ102" 0603 183.833,7.014 r90 bottom value=1.0k (schematic designator R128)
R129_A1 "RC0402FR-074K7L" 0402 80.572,6.66 r270 bottom value=4.70k (schematic designator R129)
R129_A2 "RC0402FR-074K7L" 0402 185.572,6.71 r270 bottom value=4.70k (schematic designator R129)
R130_A1 "ESR03EZPJ102" 0603 84.624,6.964 r270 bottom value=1.0k (schematic designator R130)
R130_A2 "ESR03EZPJ102" 0603 189.624,7.014 r270 bottom value=1.0k (schematic designator R130)
R131_A1 "CRCW040210K0FKED" 0402 53.926,31.771 r90 bottom value=10.0k (schematic designator R131)
R131_A2 "CRCW040210K0FKED" 0402 158.926,31.821 r90 bottom value=10.0k (schematic designator R131)
R132_A1 "CRCW040210K0FKED" 0402 52.438,31.771 r90 bottom value=10.0k (schematic designator R132)
R132_A2 "CRCW040210K0FKED" 0402 157.438,31.821 r90 bottom value=10.0k (schematic designator R132)
R133_A1 "CRCW040210K0FKED" 0402 50.95,31.771 r90 bottom value=10.0k (schematic designator R133)
R133_A2 "CRCW040210K0FKED" 0402 155.95,31.821 r90 bottom value=10.0k (schematic designator R133)
R134_A1 "CRCW040210K0FKED" 0402 55.414,31.771 r90 bottom value=10.0k (schematic designator R134)
R134_A2 "CRCW040210K0FKED" 0402 160.414,31.821 r90 bottom value=10.0k (schematic designator R134)
R135_A1 "CRCW040210K0FKED" 0402 49.462,31.771 r90 bottom value=10.0k (schematic designator R135)
R135_A2 "CRCW040210K0FKED" 0402 154.462,31.821 r90 bottom value=10.0k (schematic designator R135)
R136_A1 "CRCW040210K0FKED" 0402 44.997,31.771 r90 bottom value=10.0k (schematic designator R136)
R136_A2 "CRCW040210K0FKED" 0402 149.997,31.821 r90 bottom value=10.0k (schematic designator R136)
R137_A1 "CRCW040210K0FKED" 0402 47.974,31.771 r90 bottom value=10.0k (schematic designator R137)
R137_A2 "CRCW040210K0FKED" 0402 152.974,31.821 r90 bottom value=10.0k (schematic designator R137)
R138_A1 "CRCW040210K0FKED" 0402 46.486,31.771 r90 bottom value=10.0k (schematic designator R138)
R138_A2 "CRCW040210K0FKED" 0402 151.486,31.821 r90 bottom value=10.0k (schematic designator R138)
R140_A1 "CRCW04021K00JNED" 0402 46.491,29.301 r90 bottom value=1.0k (schematic designator R140)
R140_A2 "CRCW04021K00JNED" 0402 151.491,29.351 r90 bottom value=1.0k (schematic designator R140)
R141_A1 "CRCW04021K00JNED" 0402 76.298,86.737 r90 bottom value=1.0k (schematic designator R141)
R141_A2 "CRCW04021K00JNED" 0402 181.298,86.787 r90 bottom value=1.0k (schematic designator R141)
R143_A1 "CRCW04021K00JNED" 0402 47.984,29.301 r90 bottom value=1.0k (schematic designator R143)
R143_A2 "CRCW04021K00JNED" 0402 152.984,29.351 r90 bottom value=1.0k (schematic designator R143)
R144_A1 "AC0402FR-07100KL" 0402 77.624,86.737 r90 bottom value=100k (schematic designator R144)
R144_A2 "AC0402FR-07100KL" 0402 182.624,86.787 r90 bottom value=100k (schematic designator R144)
R146_A1 "CRCW04021K00JNED" 0402 44.997,29.301 r90 bottom value=1.0k (schematic designator R146)
R146_A2 "CRCW04021K00JNED" 0402 149.997,29.351 r90 bottom value=1.0k (schematic designator R146)
R147_A1 "CRCW04021K00JNED" 0402 74.867,86.737 r90 bottom value=1.0k (schematic designator R147)
R147_A2 "CRCW04021K00JNED" 0402 179.867,86.787 r90 bottom value=1.0k (schematic designator R147)
R149_A1 "CRCW04021K00JNED" 0402 49.477,29.301 r90 bottom value=1.0k (schematic designator R149)
R149_A2 "CRCW04021K00JNED" 0402 154.477,29.351 r90 bottom value=1.0k (schematic designator R149)
R150_A1 "AC0402FR-07100KL" 0402 78.951,86.737 r90 bottom value=100k (schematic designator R150)
R150_A2 "AC0402FR-07100KL" 0402 183.951,86.787 r90 bottom value=100k (schematic designator R150)
R152_A1 "CRCW04021K00JNED" 0402 55.451,29.301 r90 bottom value=1.0k (schematic designator R152)
R152_A2 "CRCW04021K00JNED" 0402 160.451,29.351 r90 bottom value=1.0k (schematic designator R152)
R153_A1 "RC0402FR-074K7L" 0402 56.902,31.771 r270 bottom value=4.70k (schematic designator R153)
R153_A2 "RC0402FR-074K7L" 0402 161.902,31.821 r270 bottom value=4.70k (schematic designator R153)
R155_A1 "AC0402FR-07100KL" 0402 50.665,12.523 r180 top value=100k (schematic designator R155)
R155_A2 "AC0402FR-07100KL" 0402 155.665,12.573 r180 top value=100k (schematic designator R155)
R156_A1 "CRCW04021K00JNED" 0402 50.971,29.301 r90 bottom value=1.0k (schematic designator R156)
R156_A2 "CRCW04021K00JNED" 0402 155.971,29.351 r90 bottom value=1.0k (schematic designator R156)
R157_A1 "AC0402FR-07100KL" 0402 80.277,86.737 r90 bottom value=100k (schematic designator R157)
R157_A2 "AC0402FR-07100KL" 0402 185.277,86.787 r90 bottom value=100k (schematic designator R157)
R159_A1 "CRCW04021K00JNED" 0402 52.464,29.301 r90 bottom value=1.0k (schematic designator R159)
R159_A2 "CRCW04021K00JNED" 0402 157.464,29.351 r90 bottom value=1.0k (schematic designator R159)
R160_A1 "CRCW04021K00JNED" 0402 81.603,86.737 r90 bottom value=1.0k (schematic designator R160)
R160_A2 "CRCW04021K00JNED" 0402 186.603,86.787 r90 bottom value=1.0k (schematic designator R160)
R162_A1 "AC0402FR-07100KL" 0402 50.65,13.845 r180 top value=100k (schematic designator R162)
R162_A2 "AC0402FR-07100KL" 0402 155.65,13.895 r180 top value=100k (schematic designator R162)
R163_A1 "CRCW04021K00JNED" 0402 53.958,29.301 r90 bottom value=1.0k (schematic designator R163)
R163_A2 "CRCW04021K00JNED" 0402 158.958,29.351 r90 bottom value=1.0k (schematic designator R163)
R164_A1 "AC0402FR-07100KL" 0402 82.93,86.737 r90 bottom value=100k (schematic designator R164)
R164_A2 "AC0402FR-07100KL" 0402 187.93,86.787 r90 bottom value=100k (schematic designator R164)
R165_A1 "AC0402FR-07100KL" 0402 58.746,9.902 r180 top value=100k (schematic designator R165)
R165_A2 "AC0402FR-07100KL" 0402 163.746,9.952 r180 top value=100k (schematic designator R165)
R166_A1 "AC0402FR-07100KL" 0402 57.61,16.627 r180 bottom value=100k (schematic designator R166)
R166_A2 "AC0402FR-07100KL" 0402 162.61,16.677 r180 bottom value=100k (schematic designator R166)
R167_A1 "AC0402FR-07100KL" 0402 56.43,15.371 r180 bottom value=100k (schematic designator R167)
R167_A2 "AC0402FR-07100KL" 0402 161.43,15.421 r180 bottom value=100k (schematic designator R167)
R168_A1 "CRCW040210K0FKED" 0402 54.867,31.753 r90 top value=10.0k (schematic designator R168)
R168_A2 "CRCW040210K0FKED" 0402 159.867,31.803 r90 top value=10.0k (schematic designator R168)
R169_A1 "CRCW040210K0FKED" 0402 53.515,31.753 r90 top value=10.0k (schematic designator R169)
R169_A2 "CRCW040210K0FKED" 0402 158.515,31.803 r90 top value=10.0k (schematic designator R169)
R170_A1 "CRCW040210K0FKED" 0402 52.164,31.753 r90 top value=10.0k (schematic designator R170)
R170_A2 "CRCW040210K0FKED" 0402 157.164,31.803 r90 top value=10.0k (schematic designator R170)
R171_A1 "CRCW040210K0FKED" 0402 56.218,31.753 r90 top value=10.0k (schematic designator R171)
R171_A2 "CRCW040210K0FKED" 0402 161.218,31.803 r90 top value=10.0k (schematic designator R171)
R172_A1 "CRCW040210K0FKED" 0402 50.813,31.753 r90 top value=10.0k (schematic designator R172)
R172_A2 "CRCW040210K0FKED" 0402 155.813,31.803 r90 top value=10.0k (schematic designator R172)
R173_A1 "CRCW040210K0FKED" 0402 46.759,31.753 r90 top value=10.0k (schematic designator R173)
R173_A2 "CRCW040210K0FKED" 0402 151.759,31.803 r90 top value=10.0k (schematic designator R173)
R174_A1 "CRCW040210K0FKED" 0402 49.462,31.753 r90 top value=10.0k (schematic designator R174)
R174_A2 "CRCW040210K0FKED" 0402 154.462,31.803 r90 top value=10.0k (schematic designator R174)
R175_A1 "CRCW040210K0FKED" 0402 48.11,31.753 r90 top value=10.0k (schematic designator R175)
R175_A2 "CRCW040210K0FKED" 0402 153.11,31.803 r90 top value=10.0k (schematic designator R175)
R176_A1 "CRCW04021K00JNED" 0402 48.11,29.051 r90 top value=1.0k (schematic designator R176)
R176_A2 "CRCW04021K00JNED" 0402 153.11,29.101 r90 top value=1.0k (schematic designator R176)
R177_A1 "CRCW04021K00JNED" 0402 26.584,87.212 r90 bottom value=1.0k (schematic designator R177)
R177_A2 "CRCW04021K00JNED" 0402 131.584,87.262 r90 bottom value=1.0k (schematic designator R177)
R178_A1 "CRCW04021K00JNED" 0402 49.462,29.051 r90 top value=1.0k (schematic designator R178)
R178_A2 "CRCW04021K00JNED" 0402 154.462,29.101 r90 top value=1.0k (schematic designator R178)
R179_A1 "AC0402FR-07100KL" 0402 27.951,87.212 r90 bottom value=100k (schematic designator R179)
R179_A2 "AC0402FR-07100KL" 0402 132.951,87.262 r90 bottom value=100k (schematic designator R179)
R180_A1 "CRCW04021K00JNED" 0402 46.759,29.051 r90 top value=1.0k (schematic designator R180)
R180_A2 "CRCW04021K00JNED" 0402 151.759,29.101 r90 top value=1.0k (schematic designator R180)
R181_A1 "CRCW04021K00JNED" 0402 25.217,87.212 r90 bottom value=1.0k (schematic designator R181)
R181_A2 "CRCW04021K00JNED" 0402 130.217,87.262 r90 bottom value=1.0k (schematic designator R181)
R182_A1 "CRCW04021K00JNED" 0402 50.813,29.051 r90 top value=1.0k (schematic designator R182)
R182_A2 "CRCW04021K00JNED" 0402 155.813,29.101 r90 top value=1.0k (schematic designator R182)
R183_A1 "AC0402FR-07100KL" 0402 29.317,87.212 r90 bottom value=100k (schematic designator R183)
R183_A2 "AC0402FR-07100KL" 0402 134.317,87.262 r90 bottom value=100k (schematic designator R183)
R184_A1 "CRCW04021K00JNED" 0402 56.218,29.051 r90 top value=1.0k (schematic designator R184)
R184_A2 "CRCW04021K00JNED" 0402 161.218,29.101 r90 top value=1.0k (schematic designator R184)
R185_A1 "RC0402FR-074K7L" 0402 57.902,27.934 r90 top value=4.70k (schematic designator R185)
R185_A2 "RC0402FR-074K7L" 0402 162.902,27.984 r90 top value=4.70k (schematic designator R185)
R186_A1 "CRCW04021K00JNED" 0402 52.164,29.051 r90 top value=1.0k (schematic designator R186)
R186_A2 "CRCW04021K00JNED" 0402 157.164,29.101 r90 top value=1.0k (schematic designator R186)
R187_A1 "AC0402FR-07100KL" 0402 30.684,87.212 r90 bottom value=100k (schematic designator R187)
R187_A2 "AC0402FR-07100KL" 0402 135.684,87.262 r90 bottom value=100k (schematic designator R187)
R188_A1 "CRCW04021K00JNED" 0402 53.515,29.051 r90 top value=1.0k (schematic designator R188)
R188_A2 "CRCW04021K00JNED" 0402 158.515,29.101 r90 top value=1.0k (schematic designator R188)
R189_A1 "CRCW04021K00JNED" 0402 32.051,87.212 r90 bottom value=1.0k (schematic designator R189)
R189_A2 "CRCW04021K00JNED" 0402 137.051,87.262 r90 bottom value=1.0k (schematic designator R189)
R190_A1 "CRCW04021K00JNED" 0402 54.867,29.051 r90 top value=1.0k (schematic designator R190)
R190_A2 "CRCW04021K00JNED" 0402 159.867,29.101 r90 top value=1.0k (schematic designator R190)
R191_A1 "AC0402FR-07100KL" 0402 33.417,87.212 r90 bottom value=100k (schematic designator R191)
R191_A2 "AC0402FR-07100KL" 0402 138.417,87.262 r90 bottom value=100k (schematic designator R191)
R192_A1 "CRCW04021K00FKED" 0402 73.548,70.467 r270 top value=1.00k (schematic designator R192)
R192_A2 "CRCW04021K00FKED" 0402 178.548,70.517 r270 top value=1.00k (schematic designator R192)
R193_A1 "CRCW040210K0FKED" 0402 58.446,31.771 r90 bottom value=10.0k (schematic designator R193)
R193_A2 "CRCW040210K0FKED" 0402 163.446,31.821 r90 bottom value=10.0k (schematic designator R193)
R194_A1 "CRCW04021K00FKED" 0402 71.011,70.467 r270 top value=1.00k (schematic designator R194)
R194_A2 "CRCW04021K00FKED" 0402 176.011,70.517 r270 top value=1.00k (schematic designator R194)
R195_A1 "CRCW04021K00FKED" 0402 112.055,70.462 r270 top value=1.00k (schematic designator R195)
R195_A2 "CRCW04021K00FKED" 0402 217.055,70.512 r270 top value=1.00k (schematic designator R195)
R196_A1 "CRCW04021K00JNED" 0402 58.452,29.184 r90 bottom value=1.0k (schematic designator R196)
R196_A2 "CRCW04021K00JNED" 0402 163.452,29.234 r90 bottom value=1.0k (schematic designator R196)
R197_A1 "CRCW04021K00FKED" 0402 68.474,70.467 r270 top value=1.00k (schematic designator R197)
R197_A2 "CRCW04021K00FKED" 0402 173.474,70.517 r270 top value=1.00k (schematic designator R197)
R198_A1 "CRCW04021K00FKED" 0402 109.515,70.462 r270 top value=1.00k (schematic designator R198)
R198_A2 "CRCW04021K00FKED" 0402 214.515,70.512 r270 top value=1.00k (schematic designator R198)
R199_A1 "CRCW04021K00FKED" 0402 65.936,70.467 r270 top value=1.00k (schematic designator R199)
R199_A2 "CRCW04021K00FKED" 0402 170.936,70.517 r270 top value=1.00k (schematic designator R199)
R200_A1 "CRCW04021K00FKED" 0402 106.975,70.462 r270 top value=1.00k (schematic designator R200)
R200_A2 "CRCW04021K00FKED" 0402 211.975,70.512 r270 top value=1.00k (schematic designator R200)
R201_A1 "CRCW04021K00FKED" 0402 56.438,70.467 r270 top value=1.00k (schematic designator R201)
R201_A2 "CRCW04021K00FKED" 0402 161.438,70.517 r270 top value=1.00k (schematic designator R201)
R202_A1 "CRCW04021K00FKED" 0402 104.435,70.462 r270 top value=1.00k (schematic designator R202)
R202_A2 "CRCW04021K00FKED" 0402 209.435,70.512 r270 top value=1.00k (schematic designator R202)
R203_A1 "CRCW04021K00FKED" 0402 53.906,70.432 r270 top value=1.00k (schematic designator R203)
R203_A2 "CRCW04021K00FKED" 0402 158.906,70.482 r270 top value=1.00k (schematic designator R203)
R204_A1 "CRCW04021K00FKED" 0402 101.895,70.462 r270 top value=1.00k (schematic designator R204)
R204_A2 "CRCW04021K00FKED" 0402 206.895,70.512 r270 top value=1.00k (schematic designator R204)
R205_A1 "CRCW04021K00FKED" 0402 51.348,70.432 r270 top value=1.00k (schematic designator R205)
R205_A2 "CRCW04021K00FKED" 0402 156.348,70.482 r270 top value=1.00k (schematic designator R205)
R206_A1 "CRCW04021K00FKED" 0402 99.355,70.462 r270 top value=1.00k (schematic designator R206)
R206_A2 "CRCW04021K00FKED" 0402 204.355,70.512 r270 top value=1.00k (schematic designator R206)
R207_A1 "CRCW04021K00FKED" 0402 48.791,70.432 r270 top value=1.00k (schematic designator R207)
R207_A2 "CRCW04021K00FKED" 0402 153.791,70.482 r270 top value=1.00k (schematic designator R207)
R208_A1 "CRCW04021K00FKED" 0402 96.815,70.462 r270 top value=1.00k (schematic designator R208)
R208_A2 "CRCW04021K00FKED" 0402 201.815,70.512 r270 top value=1.00k (schematic designator R208)
R209_A1 "ERJ-2GE0R00X" 0402 11.056,28.259 r270 bottom value=0 (schematic designator R209)
R209_A2 "ERJ-2GE0R00X" 0402 130.825,10.694 r0 bottom value=0 (schematic designator R209)
R210_A1 "ERJ-6GEYJ100V" 0805_HV 13.923,35.399 r270 top value=10 (schematic designator R210)
R210_A2 "ERJ-6GEYJ100V" 0805_HV 123.685,13.562 r0 top value=10 (schematic designator R210)
R211_A1 "ERJ-2GE0R00X" 0402 90.906,11.874 r0 bottom value=0 (schematic designator R211)
R211_A2 "ERJ-2GE0R00X" 0402 232.079,27.89 r90 bottom value=0 (schematic designator R211)
R212_A1 "ERJ-6GEYJ100V" 0805_HV 98.654,13.727 r0 top value=10 (schematic designator R212)
R212_A2 "ERJ-6GEYJ100V" 0805_HV 230.226,35.638 r90 top value=10 (schematic designator R212)
R213_A1 "CRCW04021K00FKED" 0402 46.233,70.432 r270 top value=1.00k (schematic designator R213)
R213_A2 "CRCW04021K00FKED" 0402 151.233,70.482 r270 top value=1.00k (schematic designator R213)
R214_A1 "CRCW04021K00FKED" 0402 94.275,70.462 r270 top value=1.00k (schematic designator R214)
R214_A2 "CRCW04021K00FKED" 0402 199.275,70.512 r270 top value=1.00k (schematic designator R214)
R215_A1 "ERJ-8ENF80R6V" 1206 12.473,38.907 r0 top value=80.6 (schematic designator R215)
R215_A2 "ERJ-8ENF80R6V" 1206 120.177,12.112 r90 top value=80.6 (schematic designator R215)
R216_A1 "CRCW04021K00FKED" 0402 43.676,70.432 r270 top value=1.00k (schematic designator R216)
R216_A2 "CRCW04021K00FKED" 0402 148.676,70.482 r270 top value=1.00k (schematic designator R216)
R217_A1 "CRCW04021K00FKED" 0402 86.233,70.462 r270 top value=1.00k (schematic designator R217)
R217_A2 "CRCW04021K00FKED" 0402 191.233,70.512 r270 top value=1.00k (schematic designator R217)
R218_A1 "ERJ-8ENF80R6V" 1206 102.319,12.371 r90 top value=80.6 (schematic designator R218)
R218_A2 "ERJ-8ENF80R6V" 1206 231.581,39.303 r180 top value=80.6 (schematic designator R218)
R219_A1 "CRCW04021K00FKED" 0402 41.118,70.432 r270 top value=1.00k (schematic designator R219)
R219_A2 "CRCW04021K00FKED" 0402 146.118,70.482 r270 top value=1.00k (schematic designator R219)
R220_A1 "CRCW04021K00FKED" 0402 83.696,70.467 r270 top value=1.00k (schematic designator R220)
R220_A2 "CRCW04021K00FKED" 0402 188.696,70.517 r270 top value=1.00k (schematic designator R220)
R221_A1 "ERJ-8ENF80R6V" 1206 7.278,38.907 r0 top value=80.6 (schematic designator R221)
R221_A2 "ERJ-8ENF80R6V" 1206 120.177,6.916 r90 top value=80.6 (schematic designator R221)
R222_A1 "ERJ-8ENF80R6V" 1206 102.335,7.096 r90 top value=80.6 (schematic designator R222)
R222_A2 "ERJ-8ENF80R6V" 1206 236.857,39.319 r180 top value=80.6 (schematic designator R222)
R223_A1 "CRCW04021K00FKED" 0402 38.56,70.432 r270 top value=1.00k (schematic designator R223)
R223_A2 "CRCW04021K00FKED" 0402 143.56,70.482 r270 top value=1.00k (schematic designator R223)
R224_A1 "CRCW04021K00FKED" 0402 81.159,70.467 r270 top value=1.00k (schematic designator R224)
R224_A2 "CRCW04021K00FKED" 0402 186.159,70.517 r270 top value=1.00k (schematic designator R224)
R225_A1 "ERJ-6GEYJ100V" 0805_HV 5.828,35.399 r270 top value=10 (schematic designator R225)
R225_A2 "ERJ-6GEYJ100V" 0805_HV 123.685,5.466 r0 top value=10 (schematic designator R225)
R226_A1 "ERJ-2GE0R00X" 0402 9.494,28.258 r270 bottom value=0 (schematic designator R226)
R226_A2 "ERJ-2GE0R00X" 0402 130.826,9.132 r0 bottom value=0 (schematic designator R226)
R227_A1 "ERJ-2GE0R00X" 0402 90.991,9.702 r0 bottom value=0 (schematic designator R227)
R227_A2 "ERJ-2GE0R00X" 0402 234.25,27.975 r90 bottom value=0 (schematic designator R227)
R228_A1 "ERJ-6GEYJ100V" 0805_HV 98.654,5.766 r0 top value=10 (schematic designator R228)
R228_A2 "ERJ-6GEYJ100V" 0805_HV 238.186,35.638 r90 top value=10 (schematic designator R228)
R229_A1 "CRCW04021K00FKED" 0402 36.003,70.432 r270 top value=1.00k (schematic designator R229)
R229_A2 "CRCW04021K00FKED" 0402 141.003,70.482 r270 top value=1.00k (schematic designator R229)
R230_A1 "CRCW04021K00FKED" 0402 78.622,70.467 r270 top value=1.00k (schematic designator R230)
R230_A2 "CRCW04021K00FKED" 0402 183.622,70.517 r270 top value=1.00k (schematic designator R230)
R231_A1 "CRCW04021K00FKED" 0402 33.445,70.432 r270 top value=1.00k (schematic designator R231)
R231_A2 "CRCW04021K00FKED" 0402 138.445,70.482 r270 top value=1.00k (schematic designator R231)
R232_A1 "CRCW04021K00FKED" 0402 76.085,70.467 r270 top value=1.00k (schematic designator R232)
R232_A2 "CRCW04021K00FKED" 0402 181.085,70.517 r270 top value=1.00k (schematic designator R232)
R233_A1 "AC0402FR-07100KL" 0402 29.883,18.264 r270 top value=100k (schematic designator R233)
R233_A2 "AC0402FR-07100KL" 0402 134.883,18.314 r270 top value=100k (schematic designator R233)
R234_A1 "AC0402FR-07100KL" 0402 32.668,18.264 r270 top value=100k (schematic designator R234)
R234_A2 "AC0402FR-07100KL" 0402 137.668,18.314 r270 top value=100k (schematic designator R234)
R235_A1 "AC0402FR-07100KL" 0402 31.283,18.264 r270 top value=100k (schematic designator R235)
R235_A2 "AC0402FR-07100KL" 0402 136.283,18.314 r270 top value=100k (schematic designator R235)
R236_A1 "AC0402FR-07100KL" 0402 31.786,20.93 r0 top value=100k (schematic designator R236)
R236_A2 "AC0402FR-07100KL" 0402 136.786,20.98 r0 top value=100k (schematic designator R236)
RT1_A1 "TMP6131DYAT" DYA0002A-MFG 84.617,86.712 r90 bottom value=10k (schematic designator RT1)
RT1_A2 "TMP6131DYAT" DYA0002A-MFG 189.617,86.762 r90 bottom value=10k (schematic designator RT1)
T1 "LKBMT10B" FP-LKBMT10B_SMT_XFRMR_27MM9_12MM5-MFG 9.5,57.975 r270 top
